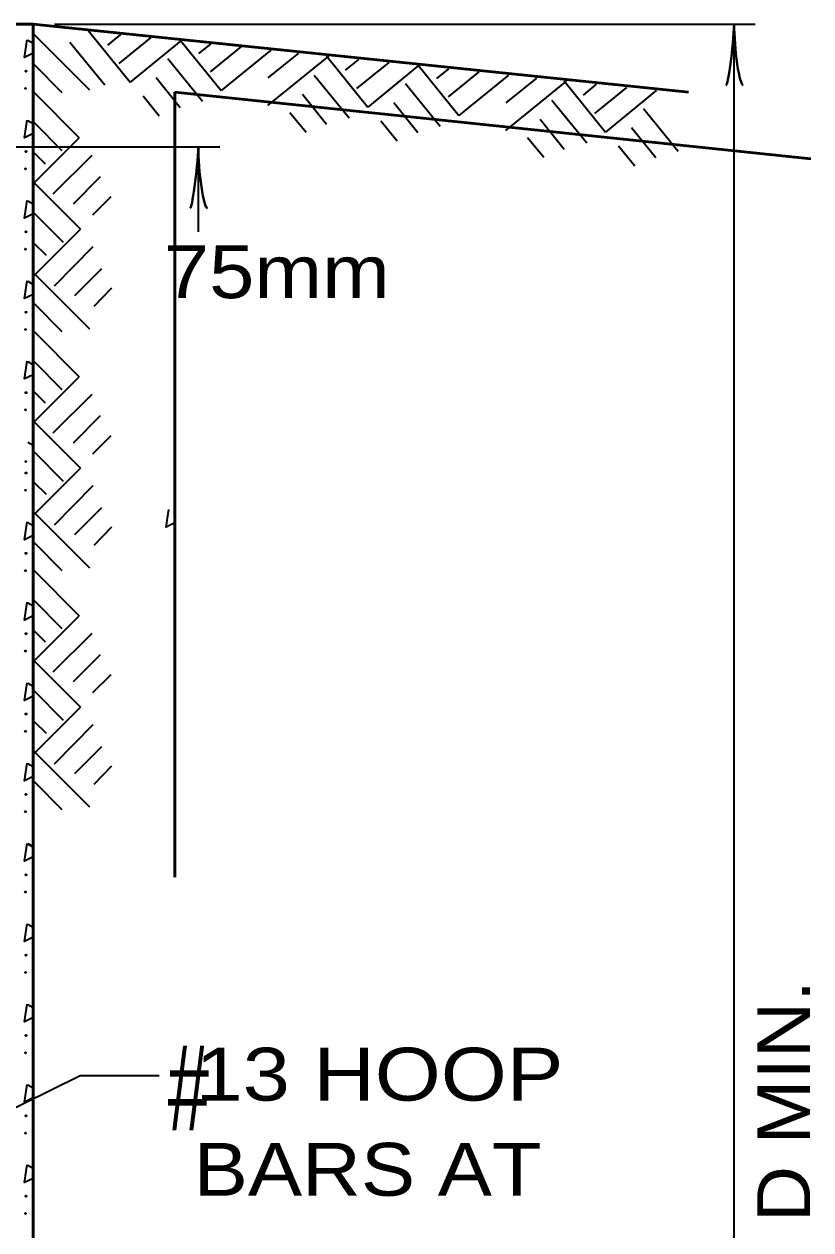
# Model space of a CAD drawing. Extents: x -39 to 816, y -16 to 528.
# Drawn here: x 507.2 to 551.8, y 228.3 to 296.7 of the extents above; entities that cross this region are included whole.
import ezdxf
from ezdxf.enums import TextEntityAlignment as Align

# ---------------------------------------------------------------- set-up
doc = ezdxf.new("R2010")
doc.units = 0
doc.header["$LTSCALE"] = 0.97
doc.layers.add('1', color=7, linetype='Continuous', lineweight=35)

msp = doc.modelspace()

# ---------------------------------------------------------------- linework, layer by layer
at = {"layer": '1', "lineweight": 53}
for p, q in [((507.7194, 296.7054), (504.0714, 296.7054)), ((507.7194, 211.4334), (507.7194, 296.7054)), ((507.7194, 296.7054), (544.8844, 292.8544)), ((515.7596, 292.8589), (551.8316, 289.0669)), ((515.7596, 248.3108), (515.7596, 292.8589)), ((507.4156, 250.2038), (507.7194, 250.0302))]:
    msp.add_line(p, q, dxfattribs=at)
at = {"layer": '1'}
for p, q in [((508.9194, 296.7054), (548.6786, 296.7054)), ((510.865, 296.3265), (513.2145, 293.4249)), ((547.4786, 174.0414), (547.4786, 296.7054)), ((507.4156, 295.8038), (507.7194, 295.6302)), ((507.7674, 296.1253), (510.9114, 292.9813)), ((509.7926, 295.6961), (511.7816, 293.2668)), ((512.679, 296.1358), (511.9379, 295.5138)), ((514.3976, 295.9551), (512.5775, 294.4813)), ((516.0922, 295.777), (513.2145, 293.4249)), ((516.0922, 295.777), (518.3777, 292.9546)), ((517.7869, 295.5988), (517.1011, 295.0435)), ((519.5054, 295.4182), (517.7645, 294.0084)), ((521.2001, 295.24), (518.3777, 292.9546)), ((524.4701, 294.8963), (521.0146, 292.0982)), ((522.7754, 295.0744), (521.0345, 293.6647)), ((524.3507, 294.9088), (526.7002, 292.0073)), ((507.7674, 294.4213), (509.3514, 292.8373)), ((515.3587, 294.7681), (517.3238, 292.3414)), ((526.1647, 294.7181), (525.4236, 294.0962)), ((527.8832, 294.5374), (526.0632, 293.0637)), ((529.5779, 294.3593), (526.7002, 292.0073)), ((529.5779, 294.3593), (531.8634, 291.5369)), ((514.6893, 293.6801), (516.0563, 291.992)), ((523.6574, 293.8233), (525.6464, 291.3941)), ((531.2726, 294.1812), (530.5868, 293.6258)), ((532.9911, 294.0005), (531.2502, 292.5908)), ((534.6858, 293.8223), (531.8634, 291.5369)), ((536.2611, 293.6567), (534.5202, 292.247)), ((507.7674, 292.8373), (510.3354, 290.2693)), ((528.8444, 293.3505), (530.8095, 290.9237)), ((537.9557, 293.4786), (534.5003, 290.6805)), ((537.8364, 293.4911), (540.1859, 290.5896)), ((539.6504, 293.3004), (538.9093, 292.6785)), ((541.3689, 293.1198), (539.5489, 291.646)), ((543.0636, 292.9416), (540.1859, 290.5896)), ((513.9533, 292.6474), (514.8718, 291.5132)), ((522.988, 292.7354), (524.355, 291.0472)), ((528.175, 292.2625), (529.542, 290.5743)), ((537.1431, 292.4057), (539.132, 289.9764)), ((522.2759, 291.7001), (523.1968, 290.5898)), ((542.3301, 291.9328), (544.2952, 289.5061)), ((507.4156, 291.2438), (507.7194, 291.0702)), ((507.7674, 291.1333), (509.3514, 289.5493)), ((527.439, 291.2298), (528.3575, 290.0955)), ((536.4737, 291.3177), (537.8407, 289.6295)), ((541.6607, 290.8448), (543.0277, 289.1567)), ((507.7674, 287.7013), (510.3354, 290.2693)), ((535.7616, 290.2825), (536.6825, 289.1721)), ((504.9834, 289.7454), (518.3034, 289.7454)), ((517.0794, 289.7454), (517.0794, 284.9214)), ((540.9247, 289.8121), (541.8431, 288.6779)), ((507.7674, 289.4053), (508.3914, 288.7813)), ((508.8474, 287.0773), (511.0554, 289.2853)), ((509.9994, 286.5253), (511.5354, 288.0613)), ((507.7674, 287.7013), (510.4074, 285.0853)), ((507.4156, 286.6838), (507.7194, 286.5102)), ((511.1034, 285.9013), (512.1354, 286.9333)), ((507.7674, 285.9973), (509.4234, 284.3413)), ((507.7674, 282.4453), (510.4074, 285.0853)), ((507.7674, 284.2693), (508.4634, 283.5973)), ((508.9194, 281.8693), (511.1274, 284.1013)), ((510.0714, 281.3173), (511.6074, 282.8533)), ((507.4156, 282.1238), (507.7194, 281.9502)), ((507.7674, 282.5653), (510.9114, 279.4213)), ((511.1754, 280.7173), (512.1834, 281.7493)), ((507.7674, 280.8613), (509.3514, 279.2773)), ((507.7674, 279.2773), (510.3354, 276.7093)), ((507.4156, 277.5638), (507.7194, 277.3902)), ((507.7674, 277.5733), (509.3514, 275.9893)), ((507.7674, 274.1413), (510.3354, 276.7093)), ((507.7674, 275.8453), (508.3914, 275.2213)), ((508.8474, 273.5173), (511.0554, 275.7253)), ((509.9994, 272.9653), (511.5354, 274.5013)), ((507.7674, 274.1413), (510.4074, 271.5253)), ((507.4156, 273.0038), (507.7194, 272.8302)), ((511.1034, 272.3413), (512.1354, 273.3733)), ((507.7674, 272.4373), (509.4234, 270.7813)), ((507.7674, 268.8853), (510.4074, 271.5253)), ((507.7674, 270.7093), (508.4634, 270.0373)), ((508.9194, 268.3093), (511.1274, 270.5413)), ((507.7674, 269.0053), (510.9114, 265.8613)), ((510.0714, 267.7573), (511.6074, 269.2933)), ((507.4156, 268.4438), (507.7194, 268.2702)), ((511.1754, 267.1573), (512.1834, 268.1893)), ((507.7674, 267.3013), (509.3514, 265.7173)), ((507.7674, 265.7173), (510.3354, 263.1493)), ((507.4156, 263.8838), (507.7194, 263.7102)), ((507.7674, 264.0133), (509.3514, 262.4293)), ((507.7674, 260.5813), (510.3354, 263.1493)), ((507.7674, 262.2853), (508.3914, 261.6613)), ((508.8474, 259.9573), (511.0554, 262.1653)), ((509.9994, 259.4053), (511.5354, 260.9413)), ((507.7674, 260.5813), (510.4074, 257.9653)), ((507.4156, 259.3238), (507.7194, 259.1502)), ((511.1034, 258.7813), (512.1354, 259.8133)), ((507.7674, 258.8773), (509.4234, 257.2213)), ((507.7674, 255.3253), (510.4074, 257.9653)), ((507.7674, 257.1493), (508.4634, 256.4773)), ((508.9194, 254.7493), (511.1274, 256.9813)), ((507.7674, 255.4453), (510.9114, 252.3013)), ((510.0714, 254.1973), (511.6074, 255.7333)), ((507.4156, 254.7638), (507.7194, 254.5902)), ((511.1754, 253.5973), (512.1834, 254.6293)), ((507.7674, 253.7413), (509.3514, 252.1573)), ((507.4156, 245.6438), (507.7194, 245.4702)), ((507.4156, 241.0838), (507.7194, 240.9102)), ((507.4156, 236.5238), (507.7194, 236.3502)), ((507.4156, 231.9638), (507.7194, 231.7902))]:
    msp.add_line(p, q, dxfattribs=at)
for points in [[(507.7194, 295.0619), (507.2236, 294.8198), (507.3676, 295.8278)], [(507.7194, 290.5019), (507.2236, 290.2598), (507.3676, 291.2678)], [(507.7194, 285.9419), (507.2236, 285.6998), (507.3676, 286.7078)], [(507.7194, 281.3819), (507.2236, 281.1398), (507.3676, 282.1478)], [(507.7194, 276.8219), (507.2236, 276.5798), (507.3676, 277.5878)], [(515.7596, 268.4154), (515.2638, 268.1733), (515.4078, 269.1813)], [(507.7194, 267.7019), (507.2236, 267.4598), (507.3676, 268.4678)], [(507.7194, 263.1419), (507.2236, 262.8998), (507.3676, 263.9078)], [(507.7194, 258.5819), (507.2236, 258.3398), (507.3676, 259.3478)], [(507.7194, 254.0219), (507.2236, 253.7798), (507.3676, 254.7878)], [(507.7194, 249.4619), (507.2236, 249.2198), (507.3676, 250.2278)], [(507.7194, 244.9019), (507.2236, 244.6598), (507.3676, 245.6678)], [(507.7194, 240.3419), (507.2236, 240.0998), (507.3676, 241.1078)], [(503.7834, 233.8014), (510.3834, 237.0654), (514.8714, 237.0654)], [(507.7194, 235.7819), (507.2236, 235.5398), (507.3676, 236.5478)], [(507.7194, 231.2219), (507.2236, 230.9798), (507.3676, 231.9878)]]:
    msp.add_lwpolyline(points, dxfattribs=at)
for centre in [(507.3086, 294.0471), (507.2767, 293.0666), (507.3086, 289.4871), (507.2767, 288.5066), (507.3086, 284.9271), (507.2767, 283.9466), (507.3086, 280.3671), (507.2767, 279.3866), (507.3086, 275.8071), (507.2767, 274.8266), (507.3045, 271.892), (507.3086, 271.2471), (507.2767, 270.2666), (507.3086, 266.6871), (507.2767, 265.7066), (507.3086, 262.1271), (507.2767, 261.1466), (507.3086, 257.5671), (507.2767, 256.5866), (507.3086, 253.0071), (507.2767, 252.0266), (507.3086, 248.4471), (507.2767, 247.4666), (507.3086, 243.8871), (507.2767, 242.9066), (507.3086, 239.3271), (507.2767, 238.3466), (507.3086, 234.7671), (507.2767, 233.7866), (507.3086, 230.2071), (507.2767, 229.2266)]:
    msp.add_circle(centre, 0.0318, dxfattribs=at)
at = {"layer": '1', "lineweight": 40}
for centre, major_axis, ratio, start_param, end_param in [((547.2247, 295.3608), (0.2108, 2.1077), 0.07063, 3.1407148, 5.41811), ((547.2247, 295.3608), (0.2108, 2.1077), 0.07063, 3.1407148, 5.41811), ((547.8102, 295.396), (-0.1874, 2.1428), 0.122415, 0.8963533, 3.1415927), ((547.8102, 295.396), (-0.1874, 2.1428), 0.122415, 0.8963533, 3.1415927), ((516.8272, 288.3963), (0.2125, 2.1246), 0.07063, 3.1407148, 5.41811), ((517.4173, 288.4317), (-0.1889, 2.16), 0.122415, 0.8963533, 3.1415927)]:
    msp.add_ellipse(centre, major_axis=major_axis, ratio=ratio, start_param=start_param, end_param=end_param, dxfattribs=at)

# ---------------------------------------------------------------- texts
at = {"layer": '1'}
for s, height, width, p in [('75mm', 3, 1.15, (515.1321, 281.1665)), ('#', 4.838, 0.65, (515.3514, 233.9454))]:
    msp.add_text(s, height=height, dxfattribs=dict(at, width=width)).set_placement(p)
at = {"layer": '1', "width": 1.1}
msp.add_text('D MIN.', height=3, rotation=90, dxfattribs=at).set_placement((551.7872, 228.7337))
at = {"layer": '1'}
for s, width, p in [(' 13 HOOP', 1.2, (526.6911, 235.6329)), ('BARS AT', 1.15, (526.6911, 230.2329))]:
    msp.add_text(s, height=3, dxfattribs=dict(at, width=width)).set_placement(p, align=Align.CENTER)

doc.saveas('drawing.dxf')
